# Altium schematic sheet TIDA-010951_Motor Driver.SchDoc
size 431 x 279 mm; Date: Not shown in title block; ApprovedBy: Not shown in title block; CheckedBy: Not shown in title block; Author: Not shown in title block; CompanyName: Not shown in title block; DrawnBy: Jenson Fang; Engineer: Not shown in title block; Organization: Not shown in title block; Address1: Not shown in title block; Address2: Not shown in title block; Address3: Not shown in title block; Address4: Not shown in title block; DocumentNumber: 2; Revision: Use project parameter SCH_Rev; SheetNumber: 2; SheetTotal: 2; PageSetup: Record=PageOptions¦CenterHorizontal=True¦CenterVertical=True¦PrintScale=1.00¦XCorrection=1.00¦YCorrection=1.00¦PrintKind=0¦BorderSize=5000000¦LeftOffset=0¦BottomOffset=0¦Orientation=2¦PaperLength=1000¦PaperWidth=1000¦Scale=100¦PaperSource=15¦PrintQuality=600¦MediaType=1¦DitherType=10¦PaperKind=Letter¦PrintScaleMode=1
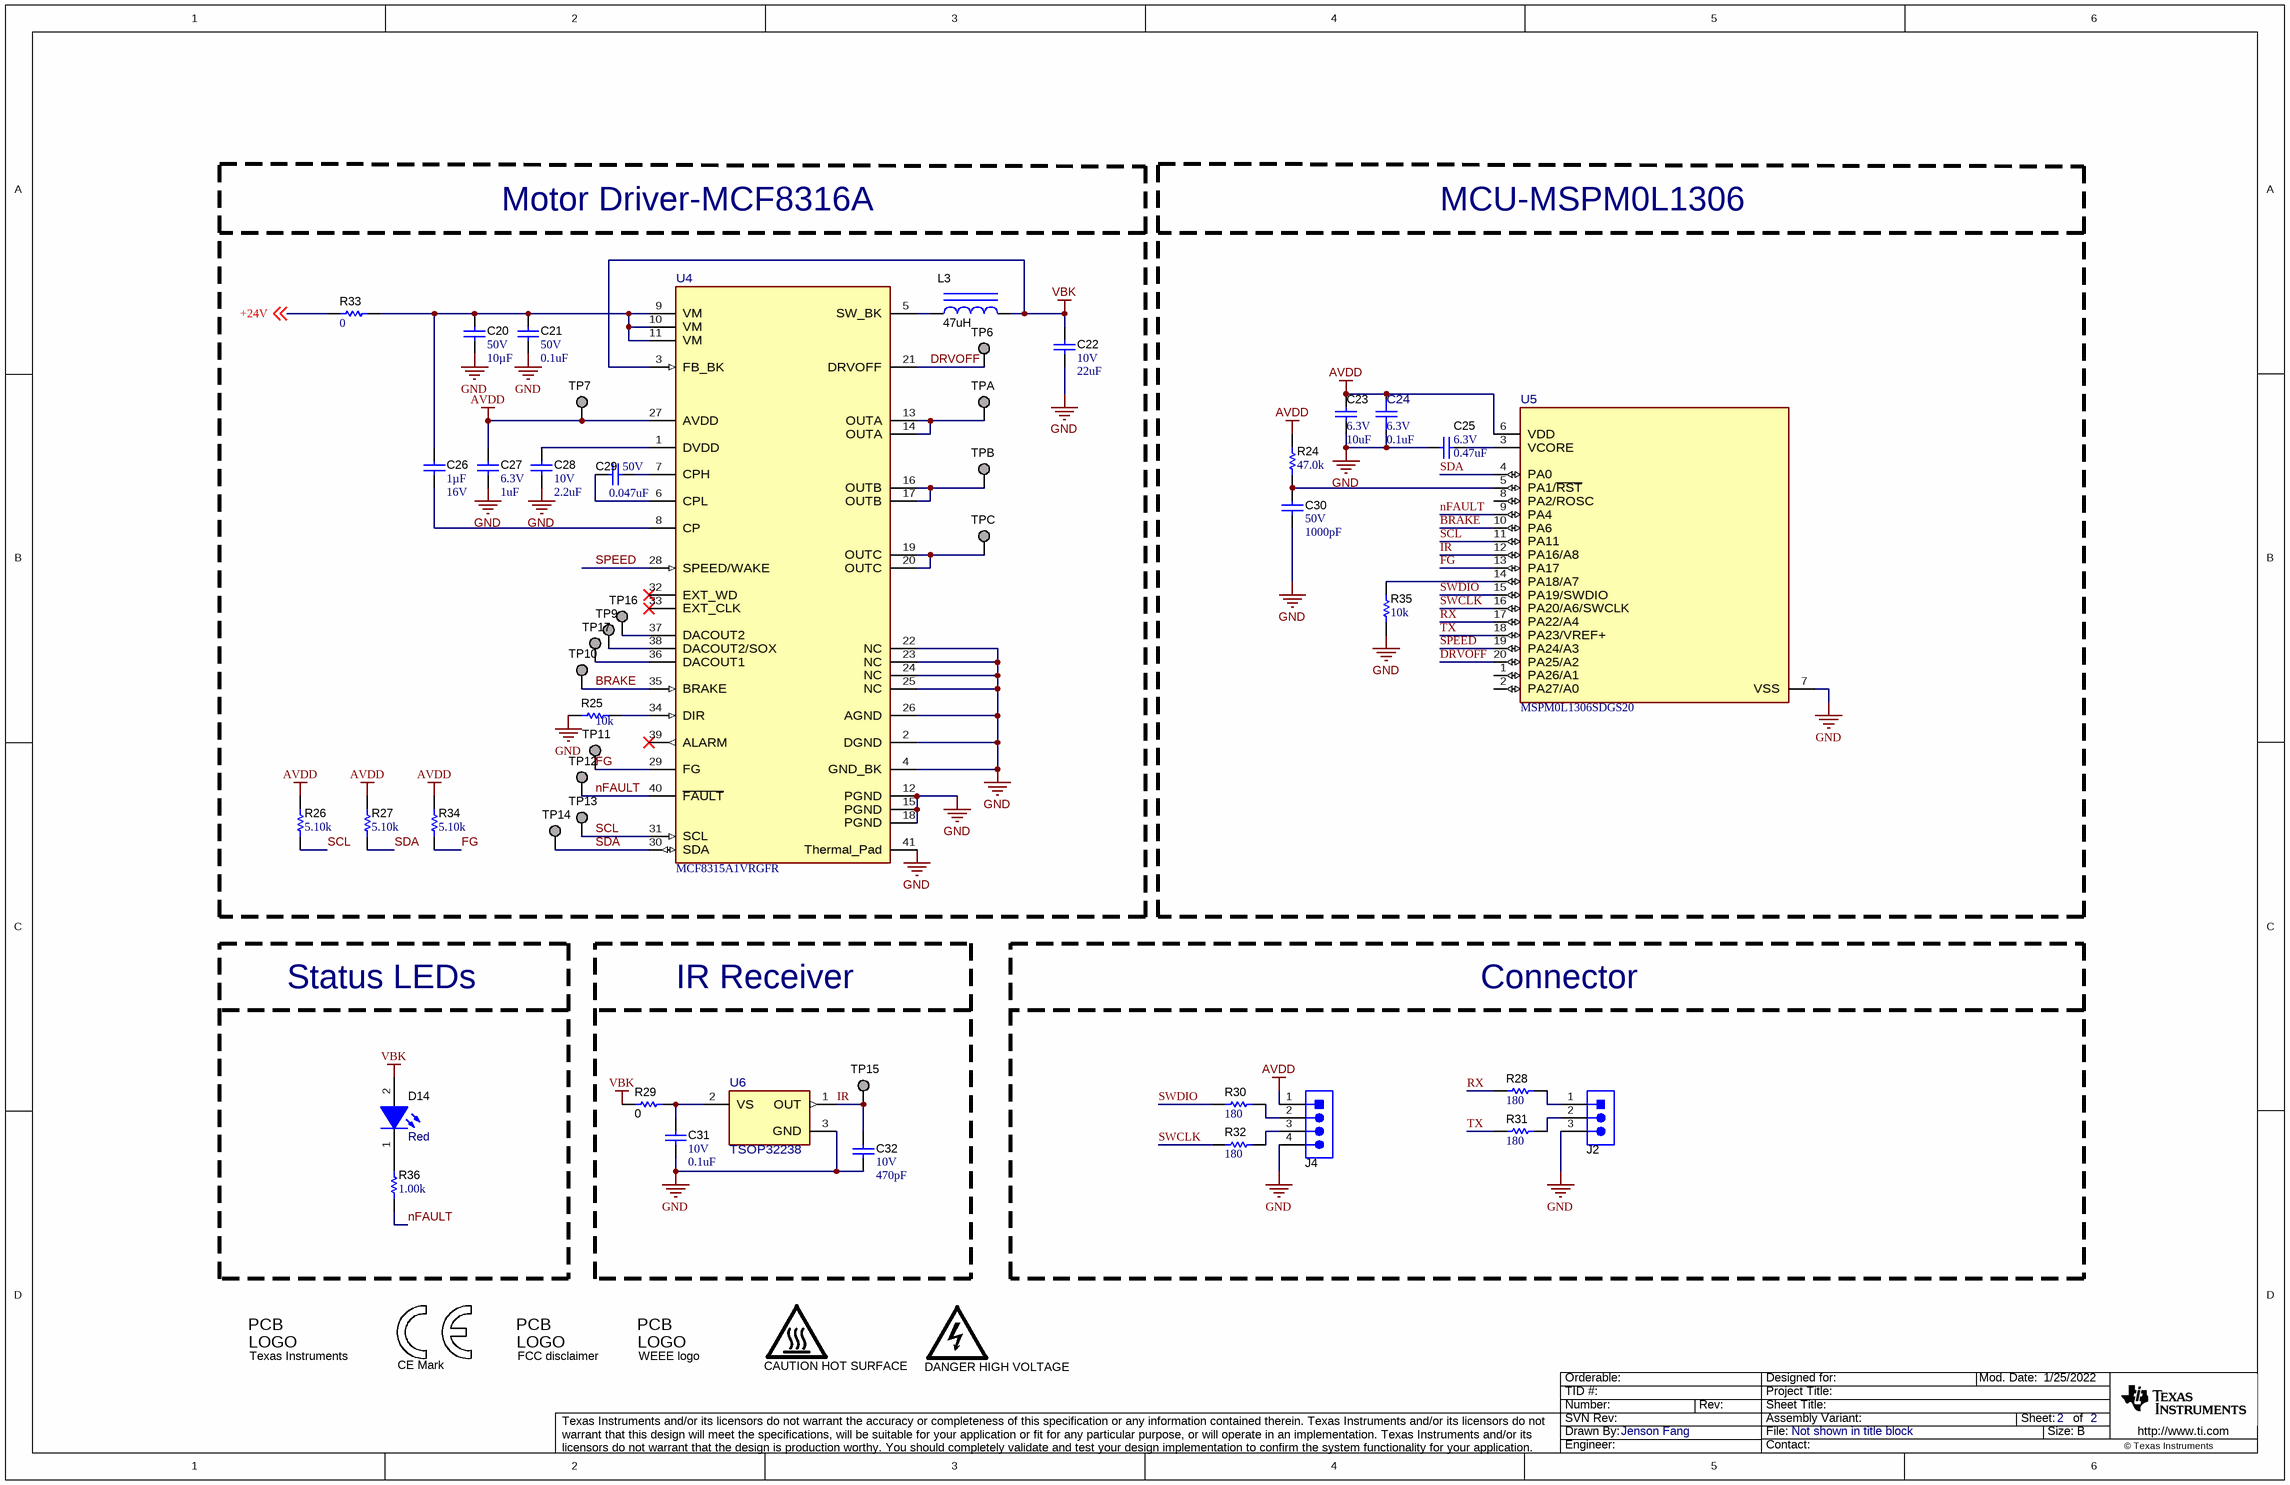
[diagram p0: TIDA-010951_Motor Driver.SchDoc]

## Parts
C20  VDC_V: 50V  ValueDisplayed: 10µF  [1206_190]  (hidden comment: UMK316BBJ106KL-T)
C21  VDC_V: 50V  ValueDisplayed: 0.1uF  [0402]  (hidden comment: C1005X7R1H104K050BB)
C22  VDC_V: 10V  ValueDisplayed: 22uF  [1206_180L]  (hidden comment: GRM31CR71A226KE15L)
C23  VDC_V: 6.3V  ValueDisplayed: 10uF  [0402]  (hidden comment: GRM155R60J106ME11)
C24  VDC_V: 6.3V  ValueDisplayed: 0.1uF  [FP-GRM033R60J104KE19D_0201-MFG]  (hidden comment: GRM033R60J104KE19D)
C25  VDC_V: 6.3V  ValueDisplayed: 0.47uF  [0201_033]  (hidden comment: GRM033R60J474KE90D)
C26  Cap_F: 1µF  VDC_V: 16V  [0603]  (hidden comment: GRM188R71C105KE15D)
C27  VDC_V: 6.3V  ValueDisplayed: 1uF  [0402]  (hidden comment: GRM155R60J105KE19D)
C28  VDC_V: 10V  ValueDisplayed: 2.2uF  [0603]  (hidden comment: LMK107BJ225KA-T)
C29  VDC_V: 50V  ValueDisplayed: 0.047uF  [0402]  (hidden comment: C1005X7R1H473K050BB)
C30  VDC_V: 50V  ValueDisplayed: 1000pF  [0402]  (hidden comment: GCM155R71H102KA37D)
C31  VDC_V: 10V  ValueDisplayed: 0.1uF  [1206_180L]  (hidden comment: GRM31CR71A226KE15L)
C32  VDC_V: 10V  ValueDisplayed: 470pF  [0603]  (hidden comment: 885012006012)
D14  value Red  [WL-SMCW_RED]  (hidden comment: 150060RS75000)
J2  61300311121  [WURTH_61300311121]  (value not drawn)
J4  61300411121  [WURTH_61300411121]  (value not drawn)
L3  ValueDisplayed: 47uH  [WE-MAIA_3015]  (hidden comment: 78438335470)
LOGO1  DANGER HIGH VOLTAGE  [IEC_HighVoltage_Small]  (no BOM)
LOGO2  CAUTION HOT SURFACE  [IEC_HotSurface_Small]  (no BOM)
Logo3  CE Mark  [CE_Mark_5mm]  (no BOM)
Logo4  Texas Instruments  [TI_Stacked_Overlay_Small]  (no BOM)
Logo5  FCC disclaimer  [FCC_disclaimer]  (no BOM)
Logo6  WEEE logo  [WEEE_Minimum]  (no BOM)
R24  ValueDisplayed: 47.0k  [0402]  (hidden comment: RC0402FR-0747KL)
R25  ValueDisplayed: 10k  [0402]  (hidden comment: CRCW040210K0JNED)
R26  ValueDisplayed: 5.10k  [0603]  (hidden comment: RC0603FR-075K1L)
R27  ValueDisplayed: 5.10k  [0603]  (hidden comment: RC0603FR-075K1L)
R28  ValueDisplayed: 180  [0402]  (hidden comment: CRCW0402180RJNED)
R29  ValueDisplayed: 0  [0603L]  (hidden comment: CRCW06035K10JNEA)
R30  ValueDisplayed: 180  [0402]  (hidden comment: CRCW0402180RJNED)
R31  ValueDisplayed: 180  [0402]  (hidden comment: CRCW0402180RJNED)
R32  ValueDisplayed: 180  [0402]  (hidden comment: CRCW0402180RJNED)
R33  ValueDisplayed: 0  [2512]  (hidden comment: CRCW25120000Z0EGHP)
R34  ValueDisplayed: 5.10k  [0603]  (hidden comment: RC0603FR-075K1L)
R35  ValueDisplayed: 10k  [0402]  (hidden comment: CRCW040210K0JNED)
R36  ValueDisplayed: 1.00k  [0402]  (hidden comment: ERA2AED102X)
TP6  TP_H0.45P0.75  [TP_H045P075]  (value not drawn)  (no BOM)
TP7  TP_H0.45P0.75  [TP_H045P075]  (value not drawn)  (no BOM)
TP9  TP_H0.45P0.75  [TP_H045P075]  (value not drawn)  (no BOM)
TP10  TP_H0.45P0.75  [TP_H045P075]  (value not drawn)  (no BOM)
TP11  TP_H0.45P0.75  [TP_H045P075]  (value not drawn)  (no BOM)
TP12  TP_H0.45P0.75  [TP_H045P075]  (value not drawn)  (no BOM)
TP13  TP_H0.45P0.75  [TP_H045P075]  (value not drawn)  (no BOM)
TP14  TP_H0.45P0.75  [TP_H045P075]  (value not drawn)  (no BOM)
TP15  TP_H0.45P0.75  [TP_H045P075]  (value not drawn)  (no BOM)
TP16  TP_H0.45P0.75  [TP_H045P075]  (value not drawn)  (no BOM)
TP17  TP_H0.45P0.75  [TP_H045P075]  (value not drawn)  (no BOM)
TPA  TP_H0.45P0.75  [TP_H045P075]  (value not drawn)  (no BOM)
TPB  TP_H0.45P0.75  [TP_H045P075]  (value not drawn)  (no BOM)
TPC  TP_H0.45P0.75  [TP_H045P075]  (value not drawn)  (no BOM)
U4  MCF8315A1VRGFR  [RGF0040E-IPC_B]
U5  MSPM0L1306SDGS20  [DGS0020A-MFG]
U6  TSOP32238  [FP-TSOP32238_SIP3-MFG]

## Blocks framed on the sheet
Motor Driver-MCF8316A: C20-C22 C26-C29 L3 R25-R27 R33 R34 TP6 TP7 TP9-TP14 TP16 TP17 TPA TPB TPC U4
MCU-MSPM0L1306: C23-C25 C30 R24 R35 U5
Status LEDs: D14 R36
IR Receiver: C31 C32 R29 TP15 U6
Connector: J2 J4 R28 R30-R32

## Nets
AVDD: C23.1 C24.2 C27.1 J4.1 R24.2 R26.2 R27.2 R34.2 TP7.1 U4.27(AVDD) U5.6(VDD)
GND: C20.2 C21.2 C22.2 C23.2 C24.1 C25.1 C27.2 C28.2 C30.2 C31.2 C32.2 J2.3 J4.4 R25.2 R35.2 U4.2(DGND) U4.4(GND_BK) U4.12(PGND) U4.15(PGND) U4.18(PGND) U4.22(NC) U4.23(NC) U4.24(NC) U4.25(NC) U4.26(AGND) U4.41(Thermal_Pad) U5.7(VSS) U6.3(GND)
VBK: C22.1 D14.2(A) L3.2 R29.2 U4.3(FB_BK)
+24V: R33.1 ; off-sheet +24V
BRAKE: TP10.1 U4.35(BRAKE) U5.10(PA6)
DRVOFF: TP6.1 U4.21(DRVOFF) U5.20(PA25/A2)
FG: R34.1 TP11.1 U4.29(FG) U5.13(PA17)
IR: C32.1 TP15.1 U5.12(PA16/A8) U6.1(OUT)
nFAULT: R36.1 TP12.1 U4.40(~{FAULT}) U5.9(PA4)
RX: R28.1 U5.17(PA22/A4)
SCL: R26.1 TP13.1 U4.31(SCL) U5.11(PA11)
SDA: R27.1 TP14.1 U4.30(SDA) U5.4(PA0)
SPEED: U4.28(SPEED/WAKE) U5.19(PA24/A3)
SWCLK: R32.1 U5.16(PA20/A6/SWCLK)
SWDIO: R30.1 U5.15(PA19/SWDIO)
TX: R31.1 U5.18(PA23/VREF+)
NetC20_1: C20.1 C21.1 C26.1 R33.2 U4.9(VM) U4.10(VM) U4.11(VM)
NetC25_2: C25.2 U5.3(VCORE)
NetC26_2: C26.2 U4.8(CP)
NetC28_1: C28.1 U4.1(DVDD)
NetC29_1: C29.1 U4.6(CPL)
NetC29_2: C29.2 U4.7(CPH)
NetC30_1: C30.1 R24.1 U5.5(PA1/~{RST})
NetC31_1: C31.1 R29.1 U6.2(VS)
NetD14_1: D14.1(K) R36.2
NetJ2_1: J2.1 R28.2
NetJ2_2: J2.2 R31.2
NetJ4_2: J4.2 R30.2
NetJ4_3: J4.3 R32.2
NetL3_1: L3.1 U4.5(SW_BK)
NetR25_1: R25.1 U4.34(DIR)
NetR35_1: R35.1 U5.14(PA18/A7)
NetTP9_1: TP9.1 U4.38(DACOUT2/SOX)
NetTP16_1: TP16.1 U4.37(DACOUT2)
NetTP17_1: TP17.1 U4.36(DACOUT1)
NetTPA_1: TPA.1 U4.13(OUTA) U4.14(OUTA)
NetTPB_1: TPB.1 U4.16(OUTB) U4.17(OUTB)
NetTPC_1: TPC.1 U4.19(OUTC) U4.20(OUTC)

Not connected (* = marked no-connect by the designer): U4 32(EXT_WD)* 33(EXT_CLK)* 39(ALARM)*; U5 1(PA26/A1) 2(PA27/A0) 8(PA2/ROSC)

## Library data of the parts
C20 = CMP-0086153-1: CAP, CERM, 10 µF, 50 V,+/- 10%, X5R, 1206; Manufacturer: Taiyo Yuden; Polarized: N; SizeX_mm: 3.2; TaMax_C: 85°C; SizeY_mm: 1.6; AEC Category: Q200; SizeArea_mm2: 5.12; Cap_Case: 1206; SizeAreaWB_mm2: 10.92; TaMin_C: -55°C; SizeZ_mm: 1.9; U/M: EA; Value: 10uF
C21 = CMP-0006297-2: CAP, CERM, 0.1 uF, 50 V, +/- 10%, X7R, 0402; Manufacturer: TDK; TaMin_C: -55°C; ESR_ohm: 0.039064; Polarized: N; SizeAreaWB_mm2: 3; Value1: 0.039064 ohm; U/M: EA; Value: 0.1uF; TaMax_C: 125°C; SizeZ_mm: 0.6; SizeX_mm: 1; SizeY_mm: 0.5; Cap_F: 100nF; IRMS_A: 8.14669dA; AEC Category: Q200
C22 C31 = CMP-0008959-2: CAP, CERM, 22 uF, 10 V, +/- 10%, X7R, 1206; Manufacturer: MuRata; TaMin_C: -55°C; Polarized: N; SizeAreaWB_mm2: 10.92; Value1: Unknown; U/M: EA; Value: 22uF; TaMax_C: 125°C; SizeZ_mm: 1.8; SizeX_mm: 3.2; SizeY_mm: 1.6; Cap_Case: 1206; SizeArea_mm2: 5.12; Cap_F: 22µF; AEC Category: Q200
C23 = CMP-0006533-1: CAP, CERM, 10 uF, 6.3 V, +/- 20%, X5R, 0402; Manufacturer: MuRata; TaMin_C: -55°C; Polarized: N; SizeAreaWB_mm2: 3; Value1: Unknown; U/M: EA; Value: 10uF; TaMax_C: 85°C; SizeZ_mm: 0.6; SizeX_mm: 1; SizeY_mm: 0.5; Cap_F: 10µF; AEC Category: Q200
C24 = CMP-0088531-2: 0.1µF ±10% 6.3V Ceramic Capacitor X5R 0201 (0603 Metric); Manufacturer: Murata; AEC Qualified: No; SizeZ_mm: 0.33mm; TempCo: 15%; Cap_F: 100nF
C25 = CMP-0009702-2: CAP, CERM, 0.47 uF, 6.3 V, +/- 10%, X5R, 0201; Manufacturer: MuRata; TaMin_C: -55°C; Polarized: N; SizeAreaWB_mm2: 2.08; Value1: Unknown; U/M: EA; Value: 0.47uF; TaMax_C: 85°C; SizeZ_mm: 0.33; SizeX_mm: 0.6; SizeY_mm: 0.3; Cap_Case: 0201; SizeArea_mm2: 0.18; Cap_F: 470nF; AEC Category: Q200
C26 = CMP-0007380-4: CAP, CERM, 1 uF, 16 V, +/- 10%, X7R, 0603; Manufacturer: MuRata; TaMin_C: -55°C; Polarized: N; SizeAreaWB_mm2: 4.68; Value1: Unknown; U/M: EA; Value: 1uF; TaMax_C: 125°C; SizeZ_mm: 1; SizeX_mm: 1.6; SizeY_mm: 0.8; SizeArea_mm2: 1.28; AEC Category: Q200
C27 = CMP-0006532-2: CAP, CERM, 1 uF, 6.3 V, +/- 10%, X5R, 0402; Manufacturer: MuRata; TaMin_C: -55°C; Polarized: N; SizeAreaWB_mm2: 3; Value1: Unknown; U/M: EA; Value: 1uF; TaMax_C: 85°C; SizeZ_mm: 0.6; SizeX_mm: 1; SizeY_mm: 0.5; Cap_F: 1µF; AEC Category: Q200
C28 = CMP-0007506-5: CAP, CERM, 2.2 uF, 10 V, +/- 10%, X5R, 0603; Manufacturer: Taiyo Yuden; TaMin_C: -55°C; Polarized: N; SizeAreaWB_mm2: 4.68; Value1: Unknown; U/M: EA; Value: 2.2uF; TaMax_C: 85°C; SizeZ_mm: 1; SizeX_mm: 1.6; SizeY_mm: 0.8; SizeArea_mm2: 1.28; Cap_F: 2.2µF; AEC Category: Q200
C29 = CMP-0006298-2: CAP, CERM, 0.047 uF, 50 V, +/- 10%, X7R, 0402; Manufacturer: TDK; TaMin_C: -55°C; ESR_ohm: 0.06407; Polarized: N; SizeAreaWB_mm2: 3; Value1: 0.06407 ohm; U/M: EA; SizeZ_mm: 0.6; SizeX_mm: 1; SizeY_mm: 0.5; Cap_F: 47nF; IRMS_A: 6.46122dA; AEC Category: Q200; TaMax_C: 125°C
C30 = CMP-0006354-2: CAP, CERM, 1000 pF, 50 V, +/- 10%, X7R, AEC-Q200 Grade 1, 0402; Manufacturer: MuRata; TaMin_C: -55°C; Polarized: N; SizeAreaWB_mm2: 3; Value1: Unknown; U/M: EA; Value: 1000pF; TaMax_C: 125°C; SizeZ_mm: 0.6; SizeX_mm: 1; SizeY_mm: 0.5; AEC Qualified: Y; Cap_F: 1nF; AEC Category: Q200
C32 = CMP-0080734-1: CAP, CERM, 470 pF, 10 V,+/- 5%, C0G/NP0, 0603; Manufacturer: Wurth Elektronik; SizeAreaWB_mm2: 4.68; SizeArea_mm2: 1.28; AEC Qualified: N; AEC Category: Q200; Value: 470pF; TaMax_C: 125°C; SizeZ_mm: 1; TaMin_C: -55°C; SizeY_mm: 0.8; U/M: EA; SizeX_mm: 1.6
D14 = CMP-0002947-3: LED, Red, SMD; Manufacturer: Wurth Elektronik; Value1: 0.072W; Vf_V: 2V; Angle: 140; Tjmax_C: 85°C; Type: AlInGaP; Vr_V: 5V; Io_A: 30mA; Power_TotalModule: 72mW
J2 = CMP-0054796-2: Header, 2.54 mm, 3x1, Gold, TH; Manufacturer: Wurth Elektronik; Pitch_mm: 2.54; Green_Lifecycle: Active; Cert_UL: Y; Shrouded: N; Green_REACh: Passed; Gender: Male; Row_Count: 1
J4 = CMP-0054798-2: Header, 2.54 mm, 4x1, Gold, TH; Manufacturer: Wurth Elektronik; Pitch_mm: 2.54; Gender: Male; Row_Count: 1; Cert_UL: Y; Shrouded: N
L3 = CMP-0064683-2: Inductor, Shielded, Powdered Iron, 47 uH, 0.39 A, 2.3 ohm, AEC-Q200 Grade 1, SMD; Manufacturer: Wurth Elektronik; Isat: 1.18A @ 20% inductance drop; Irms: 0.39A @ 40C rise; SizeAreaWB_mm2: 16; DCR_ohm: 2.3; Value1: 2.3 ohm; Value: 47uH; Imax_A: 390mA; SizeZ_mm: 1.5; SizeX_mm: 3; Value2: 0.39A; SizeArea_mm2: 9; Ind_H: 47µH; AEC Qualified: Y; AEC Grade: 1; AEC Category: Q200
LOGO1 = CMP-0074835-1: IEC 61010-1 High Voltage Warning; SymbolCreator: a0412235; Lib Reference: IEC_HighVoltage
LOGO2 = CMP-0074837-1: IEC 61010-1 Hot Surface Warning; SymbolCreator: a0412235; Lib Reference: IEC_HotSurface
Logo3 = CMP-0074844-1: SymbolCreator: a0412235
Logo4 = CMP-0074838-1: Texas Instrument Corporate Signature; SymbolCreator: a0412235; Lib Reference: TI_Logo; Library Reference: Logo
Logo5 = CMP-0074847-1: FCC_disclaimer; Library Reference: Logo
Logo6 = CMP-0074769-1
R24 = CMP-0026737-1: RES, 47.0 k, 1%, 0.0625 W, 0402; Manufacturer: Yageo America; Power_W: 62.5mW; TempCo: 100 ppm/C; Value_Code: 47k0; U/M: EA; Value: 47.0k; Res_ohm: 47k; SizeX_mm: 1; SizeY_mm: 0.5; SizeZ_mm: 0.6; AEC Qualified: N; VDC_V: 50V; AEC Category: Q200
R25 R35 = CMP-0026825-1: RES, 10 k, 5%, 0.063 W, 0402; Manufacturer: Vishay-Dale; Power_W: 63mW; TempCo: 200 ppm/C; Value_Code: 10k0; U/M: EA; Value: 10k; EIA_Code: E24; SizeX_mm: 1; SizeY_mm: 0.5; SizeZ_mm: 0.6; Value2: 0.063W; VDC_V: 50V; AEC Category: Q200
R26 R27 R34 = CMP-0023198-5: RES, 5.10 k, 1%, 0.1 W, 0603; Manufacturer: Yageo; Power_W: 100mW; TempCo: 100 ppm/C; Value_Code: 5k10; Value: 5.10k; Res_ohm: 5.1k; SizeX_mm: 1.6; SizeY_mm: 0.8; SizeZ_mm: 1; Value2: 0.1W; SizeArea_mm2: 1.28; AEC Qualified: N; VDC_V: 75V; AEC Category: Q200; SizeAreaWB_mm2: 4.68
R28 R30-R32 = CMP-0026849-3: RES, 180, 5%, 0.063 W, AEC-Q200 Grade 0, 0402; Manufacturer: Vishay-Dale; Power_W: 63mW; TempCo: 200 ppm/C; Value_Code: 180R; Value: 180; EIA_Code: E24; SizeX_mm: 1; SizeY_mm: 0.5; SizeZ_mm: 0.6; Value2: 0.063W; AEC Qualified: Y; VDC_V: 50V; AEC Category: Q200; AEC Grade: 0
R29 = CMP-0025830-4: RES, 5.1 k, 5%, 0.1 W, AEC-Q200 Grade 0, 0603; Manufacturer: Vishay-Dale; Power_W: 100mW; TempCo: 200 ppm/C; Value_Code: 5k10; Value: 5.1k; EIA_Code: E24; SizeX_mm: 1.6; SizeY_mm: 0.8; SizeZ_mm: 1; Value2: 0.1W; SizeArea_mm2: 1.28; AEC Qualified: Y; VDC_V: 75V; AEC Category: Q200
R33 = CMP-0015865-2: RES, 0, 5%, 1.5 W, AEC-Q200 Grade 0, 2512; Manufacturer: Vishay-Dale; Power_W: 1.5W; TempCo: ppm/C; Value_Code: 0000; U/M: EA; Value: 0; EIA_Code: E24; SizeX_mm: 6.3; SizeY_mm: 3.2; SizeZ_mm: 0.71; SizeArea_mm2: 20.16; AEC Qualified: Y; AEC Category: Q200
R36 = CMP-0078659-1: RES, 1.00 k, 0.5%, 0.063 W, AEC-Q200 Grade 0, 0402; Manufacturer: Panasonic; Power_W: 63mW; TempCo: 25 ppm/C; Value_Code: 1k00; Value: 1.00k; EIA_Code: E192; Res_ohm: 1k; SizeX_mm: 1; SizeY_mm: 0.5; SizeZ_mm: 0.6; Value2: 0.063W; AEC Qualified: Y; AEC Grade: 0; AEC Category: Q200
TP6 TP7 TP9-TP17 TPA TPB TPC = CMP-0003719-1: Testpoint; Manufacturer: Texas Instruments; CompType: Pad
U4 = CMP-0097009-1: Sensorless Field Oriented Control (FOC) Integrated FET BLDC Driver VQFN40; Manufacturer: Texas Instruments; TaMax_C: +125°C; Nominal Supply Current: 11-28mA; Motor Type: Brushless DC; Number Of Outputs: 3; Standoff Height: 0mm; AEC Qualified: No; SizeZ_mm: 1mm; Max Supply Voltage: 35V; TJmax_C: +150°C; TaMin_C: -40°C; Min Supply Voltage: 4.5V; Switching Frequency: 75kHz
U5 = CMP-0093964-1: Mixed-Signal Microcontrollers; Manufacturer: Texas Instruments; SizeZ_mm: 1.1mm; Number Of Adc Channels: 8; Memory Type: FLASH; AEC Qualified: No; Number Of A/D Converters: 1; Min Supply Voltage: 1.62V; TaMin_C: -40°C; Ram Size: 4KBytes; Number Of Uart Channels: 2; Max Supply Voltage: 3.6V; TaMax_C: +125°C; Standoff Height: 0.05mm; Interface: I2C,SPI,UART,LIN,IrDA,SMBus; Data Bus Width: 32bits; Number Of I/Os: 17; Core Architecture: ARM Cortex-M0+; TJmax_C: +130°C; Memory Size: 64KBytes; Number Of Timers/Counters: 4; Frequency_Fixed: 32MHz
U6 = CMP-0087036-1: IR RECEIVER, 35M, 950NM, SIP; Manufacturer: Vishay Semiconductor Opto Division; SizeZ_mm: 10.85mm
